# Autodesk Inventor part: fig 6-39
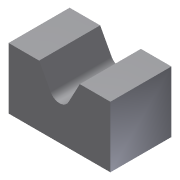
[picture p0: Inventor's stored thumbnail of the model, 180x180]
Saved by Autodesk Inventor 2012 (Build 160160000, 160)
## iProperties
Created: 2005-12
Part Number: fig 6-39
Document SubType Name: Modeling
Designer: CADCIM
Density: 1 g/cm^3
Material: Default
Author: CADCIM
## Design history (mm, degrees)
sketch "Sketch1"
  geometry: L1 (10, 15)-(25, 15); L2 (25, 15)-(25, -15); L3 (25, -15)-(-25, -15); L4 (-25, -15)-(-25, 15); L5 (-25, 15)-(-10, 15); L6 (-10, 15)-(-2, 0); L7 (-2, 0)-(2, 0); L8 (2, 0)-(10, 15); 1 further point
  constraints: 16 end point, 3 equal length, 3 parallel, 1 collinear, 1 horizontal, 1 perpendicular, 1 other
  dimensions: "d0" = 50 distance of L2.end L3.end; "d1" = 25 distance from line of point (0, 0) L2; "d2" = 30 distance of L1.end L2.end; "d3" = 15 distance of L1.start L1.end; "d4" = 15 distance between parallel lines of L1 L7; "d5" = 4 distance of L6.end L7.end; "d6" = 15 distance from line of point (0, 0) L3
extrude "Extrusion1" new body sketch "Sketch1" stored distance "d7" = 30; taper "d8" = 0 deg
fillet "Fillet4" dims "d11" = 5
body "Solid1"
